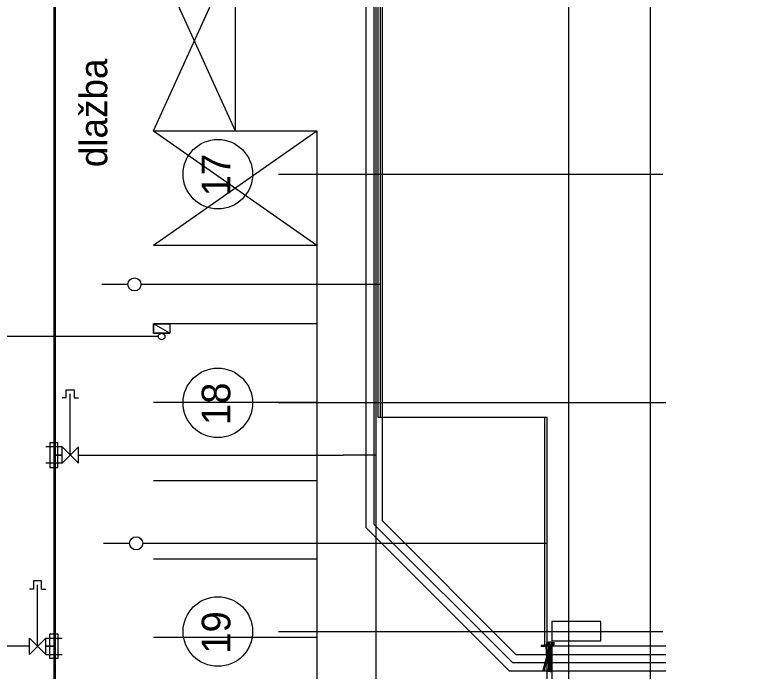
# Model space of a CAD drawing. Extents: x -264205 to -263659, y -1242401 to -1241986.
# Drawn here: x -263925.35 to -263902.98, y -1242204.1 to -1242184 of the extents above; entities that cross this region are included whole.
import ezdxf

# ---------------------------------------------------------------- set-up
doc = ezdxf.new("R2010")
doc.units = 0
for name, color, linetype in [('HESCON_OSI_STAVBY_KFA', 7, 'Continuous'), ('POPIS_2-3', 7, 'Continuous'), ('PROJEKT_OBRUBNIKY_KOMUNIKACIE', 7, 'Continuous'), ('PROJEKT_TDZ_VODOROVNE', 7, 'Continuous'), ('RAM_NA_TLAC_2-3_1-250', 7, 'Continuous'), ('SITUACIA_DSP_2D', 7, 'Continuous')]:
    doc.layers.add(name, color=color, linetype=linetype)

msp = doc.modelspace()

# ---------------------------------------------------------------- linework, layer by layer
at = {"layer": 'HESCON_OSI_STAVBY_KFA'}
for p, q in [((-263908.393, -1242083.237), (-263908.393, -1242246.707)), ((-263917.265, -1242188.882), (-263905.505, -1242188.882)), ((-263917.265, -1242188.882), (-263905.505, -1242188.882)), ((-263905.413, -1242195.882), (-263917.263, -1242195.882)), ((-263917.265, -1242202.882), (-263905.505, -1242202.882)), ((-263917.265, -1242202.882), (-263905.505, -1242202.882))]:
    msp.add_line(p, q, dxfattribs=at)
for centre in [(-263919.125, -1242188.882), (-263919.125, -1242195.882), (-263919.123, -1242202.882)]:
    msp.add_circle(centre, 1.064, dxfattribs=at)
at = {"layer": 'PROJEKT_OBRUBNIKY_KOMUNIKACIE'}
for points in [[(-263794.893, -1242227.382), (-263808.968, -1242241.457), (-263894.968, -1242241.457), (-263909.043, -1242227.382), (-263909.043, -1242196.333), (-263914.143, -1242196.333), (-263914.143, -1242132.433), (-263909.043, -1242132.433), (-263909.043, -1242101.382), (-263894.968, -1242087.307), (-263808.968, -1242087.307), (-263794.893, -1242101.382), (-263794.893, -1242227.382)], [(-263905.413, -1242203.332), (-263909.043, -1242203.332)]]:
    msp.add_lwpolyline(points, dxfattribs=at)
at = {"layer": 'PROJEKT_TDZ_VODOROVNE'}
for p, q in [((-263924.088, -1242241.458), (-263924.093, -1242087.307)), ((-263918.593, -1242141.207), (-263918.593, -1242187.557)), ((-263921.093, -1242182.062), (-263918.593, -1242187.557)), ((-263921.093, -1242187.557), (-263918.593, -1242182.062)), ((-263921.093, -1242187.557), (-263916.093, -1242187.557)), ((-263921.093, -1242187.557), (-263916.093, -1242191.057)), ((-263921.093, -1242191.057), (-263916.093, -1242187.557)), ((-263916.093, -1242187.557), (-263916.093, -1242241.458)), ((-263921.093, -1242191.057), (-263916.093, -1242191.057)), ((-263921.093, -1242193.457), (-263916.093, -1242193.457)), ((-263921.093, -1242195.857), (-263916.093, -1242195.857)), ((-263921.093, -1242198.257), (-263916.093, -1242198.257)), ((-263921.093, -1242200.657), (-263916.093, -1242200.657)), ((-263921.093, -1242203.057), (-263916.093, -1242203.057))]:
    msp.add_line(p, q, dxfattribs=at)
at = {"layer": 'RAM_NA_TLAC_2-3_1-250'}
msp.add_lwpolyline([(-263980.139, -1242275.511), (-263980.139, -1241985.511), (-263905.889, -1241985.511), (-263905.889, -1242275.511)], close=True, dxfattribs=at)
at = {"layer": 'SITUACIA_DSP_2D'}
for p, q in [((-263924.143, -1242082.64), (-263924.143, -1242185.14)), ((-263914.218, -1242196.332), (-263914.218, -1242132.432)), ((-263914.143, -1242196.333), (-263914.143, -1242132.433)), ((-263914.35, -1242168.625), (-263914.35, -1242199.59)), ((-263914.1, -1242168.521), (-263914.1, -1242199.486)), ((-263914.6, -1242168.728), (-263914.6, -1242199.693)), ((-263914.293, -1242175.482), (-263914.293, -1242210.482)), ((-263924.143, -1242185.14), (-263924.143, -1242250.14)), ((-263921.877, -1242192.257), (-263922.677, -1242192.257)), ((-263915.293, -1242192.257), (-263921.477, -1242192.257)), ((-263914.143, -1242192.257), (-263915.293, -1242192.257)), ((-263921.093, -1242193.752), (-263921.093, -1242193.462)), ((-263921.093, -1242193.462), (-263920.593, -1242193.462)), ((-263920.593, -1242193.752), (-263921.093, -1242193.462)), ((-263920.593, -1242193.752), (-263921.093, -1242193.462)), ((-263921.093, -1242193.462), (-263921.093, -1242193.752)), ((-263920.593, -1242193.462), (-263920.593, -1242193.752)), ((-263920.944, -1242193.852), (-263925.798, -1242193.852)), ((-263920.593, -1242193.752), (-263921.093, -1242193.752)), ((-263921.093, -1242193.752), (-263920.593, -1242193.752)), ((-263923.768, -1242195.732), (-263923.768, -1242195.482)), ((-263923.768, -1242195.482), (-263923.518, -1242195.482)), ((-263923.518, -1242195.482), (-263923.518, -1242195.732)), ((-263923.643, -1242197.482), (-263923.643, -1242195.607)), ((-263923.768, -1242195.732), (-263923.893, -1242195.732)), ((-263923.518, -1242195.732), (-263923.393, -1242195.732)), ((-263909.118, -1242196.332), (-263914.218, -1242196.332)), ((-263909.043, -1242196.333), (-263914.143, -1242196.333)), ((-263909.118, -1242203.332), (-263909.118, -1242196.332)), ((-263909.043, -1242227.382), (-263909.043, -1242196.333)), ((-263923.893, -1242197.232), (-263924.393, -1242197.232)), ((-263924.018, -1242197.107), (-263924.268, -1242197.107)), ((-263924.268, -1242197.107), (-263924.268, -1242197.857)), ((-263924.018, -1242197.857), (-263924.018, -1242197.107)), ((-263923.893, -1242197.732), (-263923.893, -1242197.232)), ((-263923.893, -1242197.232), (-263923.393, -1242197.732)), ((-263923.393, -1242197.232), (-263923.893, -1242197.732)), ((-263923.393, -1242197.732), (-263923.393, -1242197.232)), ((-263924.143, -1242197.482), (-263923.893, -1242197.482)), ((-263923.893, -1242197.482), (-263924.143, -1242197.482)), ((-263923.393, -1242197.482), (-263915.293, -1242197.482)), ((-263914.293, -1242197.482), (-263915.293, -1242197.482)), ((-263923.893, -1242197.732), (-263924.393, -1242197.732)), ((-263924.268, -1242197.857), (-263924.018, -1242197.857)), ((-263914.1, -1242199.486), (-263910.004, -1242203.582)), ((-263914.6, -1242199.693), (-263910.211, -1242204.082)), ((-263914.35, -1242199.59), (-263910.108, -1242203.832)), ((-263921.824, -1242200.182), (-263922.624, -1242200.182)), ((-263915.293, -1242200.182), (-263921.424, -1242200.182)), ((-263909.043, -1242200.182), (-263915.293, -1242200.182)), ((-263924.768, -1242201.332), (-263924.768, -1242201.582)), ((-263924.518, -1242201.332), (-263924.768, -1242201.332)), ((-263924.643, -1242203.332), (-263924.643, -1242201.457)), ((-263924.518, -1242201.582), (-263924.518, -1242201.332)), ((-263924.768, -1242201.582), (-263924.893, -1242201.582)), ((-263924.518, -1242201.582), (-263924.393, -1242201.582)), ((-263907.398, -1242202.57), (-263908.898, -1242202.57)), ((-263908.898, -1242202.57), (-263908.898, -1242203.17)), ((-263907.398, -1242203.17), (-263907.398, -1242202.57)), ((-263924.893, -1242203.582), (-263924.893, -1242203.082)), ((-263924.393, -1242203.082), (-263924.893, -1242203.582)), ((-263924.893, -1242203.082), (-263924.393, -1242203.582)), ((-263924.393, -1242203.582), (-263924.393, -1242203.082)), ((-263924.393, -1242203.082), (-263923.893, -1242203.082)), ((-263924.268, -1242203.707), (-263924.268, -1242202.957)), ((-263924.268, -1242202.957), (-263924.018, -1242202.957)), ((-263924.018, -1242202.957), (-263924.018, -1242203.707)), ((-263909.213, -1242203.31), (-263909.243, -1242203.318)), ((-263909.243, -1242203.318), (-263909.228, -1242203.322)), ((-263909.228, -1242203.294), (-263909.085, -1242203.294)), ((-263909.228, -1242203.294), (-263909.228, -1242203.306)), ((-263909.228, -1242203.306), (-263909.213, -1242203.31)), ((-263909.228, -1242203.322), (-263909.228, -1242203.334)), ((-263908.998, -1242203.289), (-263909.085, -1242203.291)), ((-263909.085, -1242203.291), (-263909.08, -1242203.566)), ((-263909.058, -1242203.234), (-263909.057, -1242203.29)), ((-263909.058, -1242203.234), (-263909.027, -1242203.234)), ((-263909.055, -1242203.234), (-263909.049, -1242203.224)), ((-263909.049, -1242203.244), (-263909.055, -1242203.234)), ((-263909.049, -1242203.224), (-263909.037, -1242203.224)), ((-263909.037, -1242203.244), (-263909.049, -1242203.244)), ((-263908.993, -1242203.214), (-263909.043, -1242203.214)), ((-263909.043, -1242203.218), (-263909.043, -1242203.249)), ((-263909.037, -1242203.224), (-263909.031, -1242203.234)), ((-263909.031, -1242203.234), (-263909.037, -1242203.244)), ((-263909.027, -1242203.29), (-263909.028, -1242203.234)), ((-263909.027, -1242203.254), (-263909.008, -1242203.254)), ((-263908.993, -1242203.254), (-263909.027, -1242203.254)), ((-263909.018, -1242203.254), (-263909.018, -1242203.264)), ((-263909.003, -1242203.224), (-263908.988, -1242203.224)), ((-263909.003, -1242203.273), (-263908.988, -1242203.273)), ((-263909, -1242203.217), (-263909, -1242203.231)), ((-263908.995, -1242203.217), (-263909, -1242203.217)), ((-263909, -1242203.231), (-263908.995, -1242203.231)), ((-263909, -1242203.266), (-263909, -1242203.28)), ((-263908.995, -1242203.266), (-263909, -1242203.266)), ((-263909, -1242203.28), (-263908.995, -1242203.28)), ((-263908.995, -1242203.224), (-263908.999, -1242203.224)), ((-263908.995, -1242203.273), (-263908.999, -1242203.273)), ((-263908.993, -1242203.564), (-263908.998, -1242203.289)), ((-263908.998, -1242203.294), (-263908.983, -1242203.294)), ((-263908.998, -1242203.294), (-263908.968, -1242203.294)), ((-263908.995, -1242203.232), (-263908.995, -1242203.215)), ((-263908.995, -1242203.215), (-263908.993, -1242203.215)), ((-263908.995, -1242203.231), (-263908.995, -1242203.217)), ((-263908.995, -1242203.232), (-263908.993, -1242203.232)), ((-263908.995, -1242203.281), (-263908.995, -1242203.264)), ((-263908.995, -1242203.264), (-263908.993, -1242203.264)), ((-263908.995, -1242203.28), (-263908.995, -1242203.266)), ((-263908.995, -1242203.281), (-263908.993, -1242203.281)), ((-263908.893, -1242203.208), (-263908.993, -1242203.208)), ((-263908.983, -1242203.213), (-263908.993, -1242203.213)), ((-263908.993, -1242203.213), (-263908.993, -1242203.283)), ((-263908.993, -1242203.232), (-263908.993, -1242203.215)), ((-263908.993, -1242203.281), (-263908.993, -1242203.264)), ((-263908.983, -1242203.283), (-263908.993, -1242203.283)), ((-263908.983, -1242204.103), (-263908.983, -1242203.208)), ((-263908.983, -1242203.213), (-263908.983, -1242203.283)), ((-263908.983, -1242203.224), (-263908.975, -1242203.224)), ((-263908.983, -1242203.288), (-263908.903, -1242203.288)), ((-263908.983, -1242203.294), (-263908.903, -1242203.294)), ((-263908.975, -1242203.245), (-263908.975, -1242203.224)), ((-263908.968, -1242203.334), (-263908.968, -1242203.294)), ((-263908.968, -1242203.301), (-263908.968, -1242203.326)), ((-263908.968, -1242203.301), (-263908.958, -1242203.301)), ((-263908.968, -1242203.326), (-263908.958, -1242203.326)), ((-263908.961, -1242203.335), (-263908.959, -1242203.326)), ((-263908.959, -1242203.326), (-263908.935, -1242203.332)), ((-263908.958, -1242203.301), (-263908.958, -1242203.326)), ((-263908.949, -1242203.306), (-263908.958, -1242203.313)), ((-263908.958, -1242203.313), (-263908.958, -1242203.315)), ((-263908.958, -1242203.315), (-263908.949, -1242203.322)), ((-263908.955, -1242203.288), (-263908.955, -1242203.298)), ((-263908.93, -1242203.288), (-263908.955, -1242203.288)), ((-263908.93, -1242203.298), (-263908.955, -1242203.298)), ((-263908.955, -1242203.339), (-263908.955, -1242203.329)), ((-263908.93, -1242203.329), (-263908.955, -1242203.329)), ((-263908.952, -1242203.318), (-263908.948, -1242203.329)), ((-263908.951, -1242203.308), (-263908.944, -1242203.298)), ((-263908.944, -1242203.329), (-263908.951, -1242203.32)), ((-263908.948, -1242203.329), (-263908.946, -1242203.329)), ((-263908.946, -1242203.329), (-263908.937, -1242203.322)), ((-263908.944, -1242203.298), (-263908.942, -1242203.298)), ((-263908.942, -1242203.329), (-263908.944, -1242203.329)), ((-263908.942, -1242203.298), (-263908.935, -1242203.308)), ((-263908.935, -1242203.32), (-263908.942, -1242203.329)), ((-263908.93, -1242203.288), (-263908.93, -1242203.298)), ((-263908.93, -1242203.339), (-263908.93, -1242203.329)), ((-263908.91, -1242203.245), (-263908.91, -1242203.224)), ((-263908.91, -1242203.224), (-263908.903, -1242203.224)), ((-263908.903, -1242204.103), (-263908.903, -1242203.208)), ((-263908.903, -1242203.214), (-263908.843, -1242203.214)), ((-263908.903, -1242203.294), (-263908.853, -1242203.294)), ((-263908.898, -1242203.17), (-263907.398, -1242203.17)), ((-263908.881, -1242203.254), (-263908.855, -1242203.254)), ((-263908.868, -1242203.241), (-263908.868, -1242203.267)), ((-263908.843, -1242203.208), (-263908.843, -1242203.284)), ((-263924.893, -1242203.332), (-263958.097, -1242203.332)), ((-263924.143, -1242203.332), (-263924.393, -1242203.332)), ((-263924.393, -1242203.332), (-263924.143, -1242203.332)), ((-263909.228, -1242203.334), (-263909.084, -1242203.334)), ((-263905.413, -1242203.332), (-263909.118, -1242203.332)), ((-263909.064, -1242203.439), (-263909.014, -1242203.438)), ((-263909.061, -1242203.565), (-263909.064, -1242203.439)), ((-263909.063, -1242203.449), (-263909.013, -1242203.448)), ((-263909.061, -1242203.555), (-263909.011, -1242203.554)), ((-263905.413, -1242203.332), (-263909.043, -1242203.332)), ((-263909.011, -1242203.564), (-263909.014, -1242203.438)), ((-263908.997, -1242203.334), (-263908.968, -1242203.334)), ((-263908.983, -1242203.386), (-263908.969, -1242203.333)), ((-263908.983, -1242203.54), (-263908.93, -1242203.344)), ((-263908.93, -1242203.344), (-263908.969, -1242203.333)), ((-263908.963, -1242204.098), (-263908.963, -1242203.339)), ((-263908.963, -1242203.339), (-263908.923, -1242203.339)), ((-263908.93, -1242203.339), (-263908.955, -1242203.339)), ((-263908.937, -1242203.342), (-263908.935, -1242203.332)), ((-263908.923, -1242204.098), (-263908.923, -1242203.339)), ((-263908.893, -1242226.995), (-263908.893, -1242203.332)), ((-263924.393, -1242203.582), (-263923.893, -1242203.582)), ((-263924.018, -1242203.707), (-263924.268, -1242203.707)), ((-263910.004, -1242203.582), (-263905.413, -1242203.582)), ((-263909.163, -1242204.066), (-263909.064, -1242203.69)), ((-263909.08, -1242203.566), (-263908.993, -1242203.564)), ((-263909.067, -1242203.565), (-263909.057, -1242204.046)), ((-263909.052, -1242203.788), (-263909.056, -1242203.565)), ((-263909.012, -1242203.787), (-263909.016, -1242203.564)), ((-263908.996, -1242204.045), (-263909.006, -1242203.564)), ((-263910.108, -1242203.832), (-263905.413, -1242203.832)), ((-263909.124, -1242204.077), (-263909.061, -1242203.834)), ((-263909.052, -1242203.788), (-263909.012, -1242203.787)), ((-263909.036, -1242203.809), (-263909.043, -1242203.822)), ((-263909.042, -1242203.793), (-263909.042, -1242203.788)), ((-263909.042, -1242203.793), (-263909.022, -1242203.792)), ((-263909.04, -1242203.793), (-263909.041, -1242203.794)), ((-263909.041, -1242203.8), (-263909.041, -1242203.794)), ((-263909.04, -1242203.801), (-263909.041, -1242203.8)), ((-263909.04, -1242203.793), (-263909.023, -1242203.792)), ((-263909.04, -1242203.801), (-263909.023, -1242203.8)), ((-263909.036, -1242203.8), (-263909.037, -1242203.793)), ((-263909.036, -1242203.809), (-263909.036, -1242203.801)), ((-263909.026, -1242203.809), (-263909.036, -1242203.809)), ((-263909.027, -1242203.8), (-263909.027, -1242203.793)), ((-263909.026, -1242203.809), (-263909.026, -1242203.8)), ((-263909.026, -1242203.809), (-263909.019, -1242203.822)), ((-263909.023, -1242203.792), (-263909.022, -1242203.793)), ((-263909.023, -1242203.8), (-263909.022, -1242203.8)), ((-263909.022, -1242203.792), (-263909.022, -1242203.787)), ((-263909.022, -1242203.8), (-263909.022, -1242203.793)), ((-263908.989, -1242203.965), (-263908.983, -1242203.965)), ((-263908.989, -1242204.04), (-263908.989, -1242203.965)), ((-263908.983, -1242203.965), (-263908.929, -1242203.965)), ((-263908.943, -1242203.973), (-263908.95, -1242203.976)), ((-263908.95, -1242203.976), (-263908.95, -1242203.984)), ((-263908.95, -1242203.984), (-263908.943, -1242203.988)), ((-263908.936, -1242203.976), (-263908.943, -1242203.973)), ((-263908.943, -1242203.988), (-263908.936, -1242203.984)), ((-263908.936, -1242203.984), (-263908.936, -1242203.976)), ((-263908.929, -1242204.04), (-263908.929, -1242203.965)), ((-263910.211, -1242204.082), (-263905.413, -1242204.082)), ((-263909.164, -1242204.064), (-263909.157, -1242204.035)), ((-263909.124, -1242204.077), (-263909.163, -1242204.066)), ((-263909.127, -1242204.078), (-263909.162, -1242204.069)), ((-263909.157, -1242204.035), (-263909.155, -1242204.035)), ((-263909.114, -1242204.046), (-263909.122, -1242204.075)), ((-263909.116, -1242204.046), (-263909.114, -1242204.046)), ((-263908.996, -1242204.045), (-263909.057, -1242204.046)), ((-263908.989, -1242204.04), (-263908.983, -1242204.04)), ((-263908.983, -1242204.04), (-263908.929, -1242204.04)), ((-263908.96, -1242204.096), (-263908.969, -1242204.096)), ((-263908.966, -1242204.081), (-263908.963, -1242204.081)), ((-263908.965, -1242204.096), (-263908.965, -1242204.066)), ((-263908.965, -1242204.066), (-263908.963, -1242204.066)), ((-263908.963, -1242204.098), (-263908.923, -1242204.098)), ((-263908.961, -1242204.1), (-263908.925, -1242204.1)), ((-263908.943, -1242204.018), (-263908.95, -1242204.021)), ((-263908.95, -1242204.021), (-263908.95, -1242204.029)), ((-263908.95, -1242204.029), (-263908.943, -1242204.033)), ((-263908.936, -1242204.021), (-263908.943, -1242204.018)), ((-263908.943, -1242204.033), (-263908.936, -1242204.029)), ((-263908.936, -1242204.029), (-263908.936, -1242204.021)), ((-263908.923, -1242204.066), (-263908.921, -1242204.066)), ((-263908.921, -1242204.096), (-263908.921, -1242204.066))]:
    msp.add_line(p, q, dxfattribs=at)
for centre, radius in [((-263921.677, -1242192.257), 0.2), ((-263920.844, -1242193.852), 0.1), ((-263921.624, -1242200.182), 0.2), ((-263909.043, -1242203.234), 0.0126), ((-263909.043, -1242203.234), 0.0102), ((-263908.868, -1242203.254), 0.008), ((-263909.031, -1242203.829), 0.00952), ((-263909.031, -1242203.829), 0.00645), ((-263909.031, -1242203.829), 0.005), ((-263908.943, -1242203.98), 0.0084), ((-263908.943, -1242203.98), 0.0068), ((-263908.943, -1242204.025), 0.0084), ((-263908.943, -1242204.025), 0.0068)]:
    msp.add_circle(centre, radius, dxfattribs=at)
for centre, radius, start, end in [((-263909.043, -1242203.234), 0.02, 90, 222.5496), ((-263909.043, -1242203.234), 0.015, 1.14, 181.14), ((-263909.018, -1242203.254), 0.008, 176.4167, 3.5833), ((-263908.993, -1242203.22), 0.0068, 150, 210), ((-263908.993, -1242203.227), 0.0068, 150, 210), ((-263908.993, -1242203.269), 0.0068, 150, 210), ((-263908.993, -1242203.276), 0.0068, 150, 210), ((-263908.943, -1242203.245), 0.0325, 180, 0), ((-263908.943, -1242203.314), 0.01, 323.6139, 216.3861), ((-263908.943, -1242203.314), 0.01, 308.6139, 201.3861), ((-263908.943, -1242203.314), 0.01, 143.6139, 36.3861), ((-263908.943, -1242203.314), 0.01, 233.6139, 126.3861), ((-263908.853, -1242203.284), 0.01, 270, 0), ((-263909.031, -1242203.829), 0.014, 152.4029, 29.8771), ((-263909.039, -1242203.797), 0.00432, 56.5466, 125.7334), ((-263909.039, -1242203.796), 0.00432, 236.5466, 305.7334), ((-263909.031, -1242203.809), 0.0161, 73.4401, 108.8399), ((-263909.037, -1242203.793), 0.0001, 291.9532, 1.14), ((-263909.032, -1242203.784), 0.0161, 253.4401, 288.8399), ((-263909.036, -1242203.8), 0.0001, 1.14, 70.3268), ((-263909.024, -1242203.797), 0.00432, 56.5466, 125.7334), ((-263909.024, -1242203.796), 0.00432, 236.5466, 305.7334), ((-263909.161, -1242204.065), 0.004, 165, 255), ((-263908.943, -1242203.314), 0.786, 255, 270), ((-263909.126, -1242204.074), 0.004, 255, 345), ((-263908.961, -1242204.096), 0.004, 180, 270), ((-263908.925, -1242204.096), 0.004, 270, 0)]:
    msp.add_arc(centre, radius, start, end, dxfattribs=at)

# ---------------------------------------------------------------- texts
at = {"layer": 'HESCON_OSI_STAVBY_KFA'}
for s, p in [('17', (-263918.744, -1242189.562)), ('18', (-263918.744, -1242196.562)), ('19', (-263918.742, -1242203.562))]:
    msp.add_text(s, height=0.875, rotation=90, dxfattribs=at).set_placement(p)
at = {"layer": 'POPIS_2-3'}
msp.add_text('dlažba', height=0.8438, rotation=90, dxfattribs=at).set_placement((-263922.511, -1242188.667))

doc.saveas('drawing.dxf')
